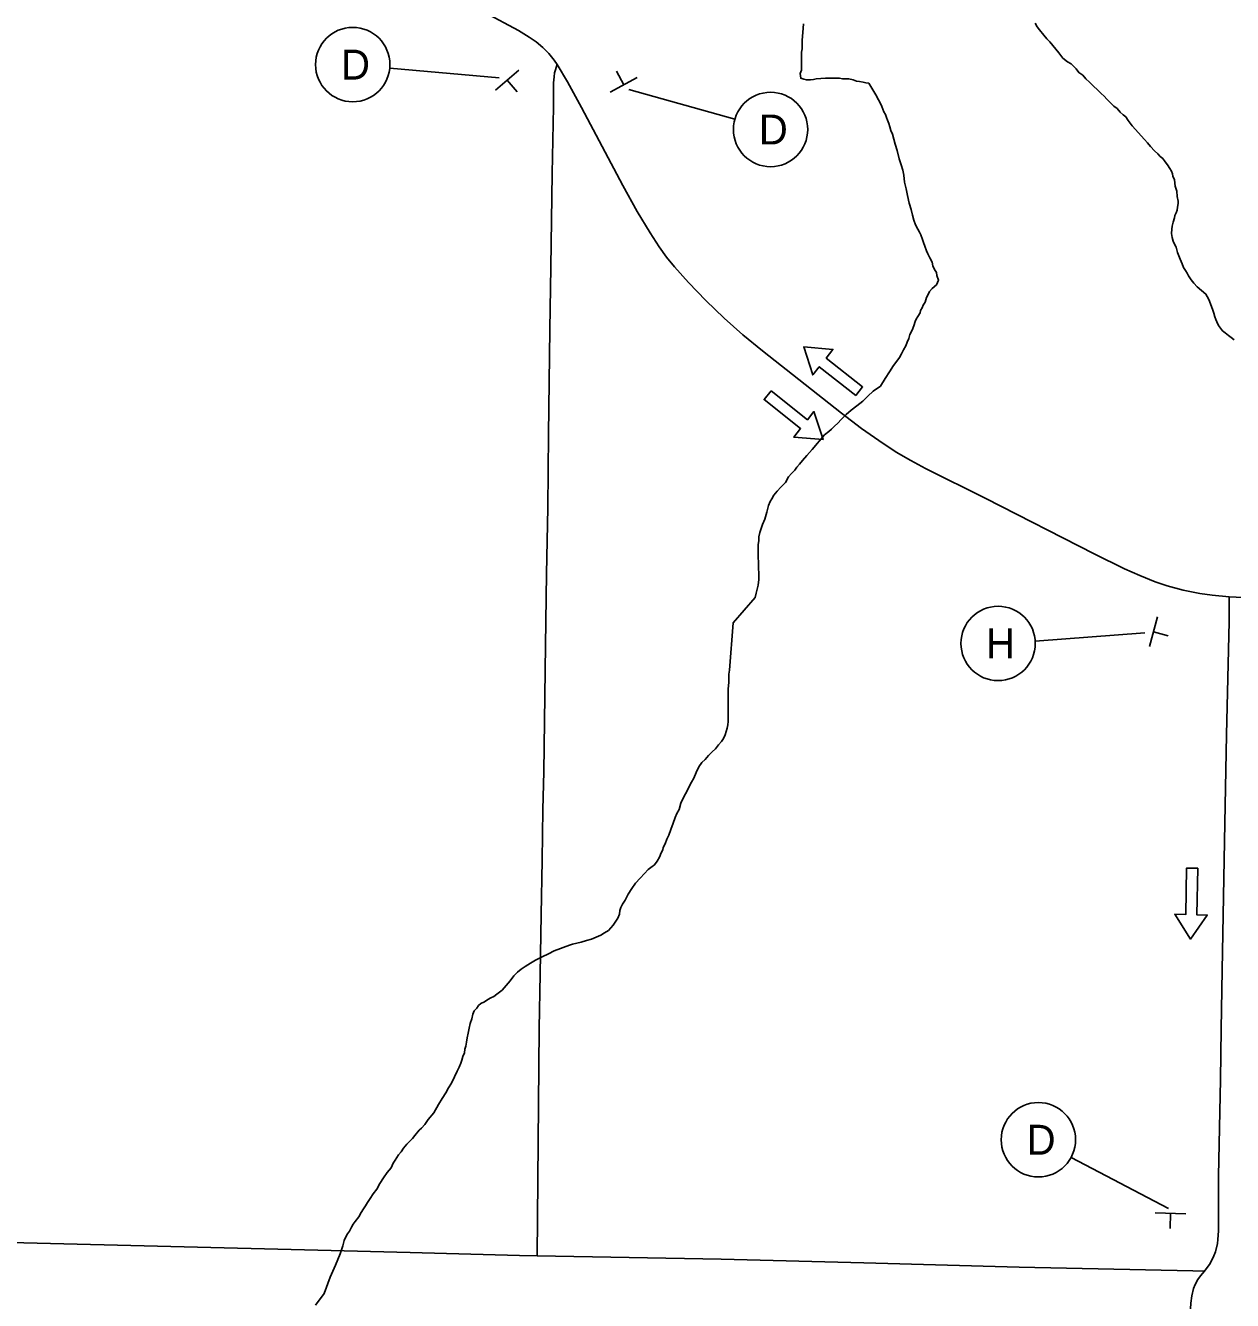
# Model space of a CAD drawing. Extents: x 1651.5 to 1685.5, y 1084.6 to 1106.6.
# Drawn here: x 1658.64 to 1664.92, y 1092.09 to 1098.72 of the extents above; entities that cross this region are included whole.
import ezdxf

# ---------------------------------------------------------------- set-up
doc = ezdxf.new("R2010")
doc.units = 0
for name, color, linetype in [('GM_X_County_Road', 7, 'Continuous'), ('GM_X_Minor_River', 7, 'Continuous'), ('GM_X_State_Route', 7, 'Continuous'), ('GM_X_Township_Road', 7, 'Continuous'), ('SH_Text', 7, 'Continuous'), ('SN_P_Signs', 7, 'Continuous')]:
    doc.layers.add(name, color=color, linetype=linetype)

msp = doc.modelspace()

# ---------------------------------------------------------------- linework, layer by layer
at = {"layer": 'GM_X_County_Road'}
for points in [[(1664.7781, 1092.2384), (1664.8083, 1092.279), (1664.8281, 1092.3184), (1664.8363, 1092.3391), (1664.8463, 1092.3822), (1664.8489, 1092.4043), (1664.8518, 1092.4484), (1664.852, 1092.7334), (1664.8626, 1093.2364), (1664.8652, 1093.499), (1664.8702, 1093.8051), (1664.8848, 1094.5707), (1664.8932, 1095.0301), (1664.908, 1095.6206), (1664.9075, 1095.7086), (1664.9073, 1095.7491)], [(1664.5833, 1088.7638), (1664.5876, 1088.9203), (1664.6035, 1089.4012), (1664.6207, 1089.904), (1664.6327, 1090.2091), (1664.6503, 1090.5818), (1664.6617, 1090.9095), (1664.6847, 1091.5685), (1664.6969, 1091.8932), (1664.7038, 1092.014), (1664.7085, 1092.0716), (1664.7131, 1092.1103), (1664.7212, 1092.1486), (1664.7305, 1092.1687), (1664.7444, 1092.1954), (1664.7575, 1092.2144), (1664.7781, 1092.2384)]]:
    msp.add_lwpolyline(points, dxfattribs=at)
at = {"layer": 'GM_X_Minor_River'}
for points in [[(1662.6906, 1098.7319), (1662.6874, 1098.6864), (1662.6842, 1098.6463), (1662.6839, 1098.6195), (1662.6836, 1098.6007), (1662.6807, 1098.5847), (1662.6806, 1098.5713), (1662.6802, 1098.5418), (1662.6795, 1098.4909), (1662.6739, 1098.4723), (1662.6763, 1098.4481), (1662.6924, 1098.4426), (1662.7058, 1098.4397), (1662.7273, 1098.4394), (1662.7434, 1098.4419), (1662.7568, 1098.4444), (1662.7811, 1098.4467), (1662.8052, 1098.4491), (1662.8214, 1098.4489), (1662.8375, 1098.4487), (1662.8509, 1098.4485), (1662.8777, 1098.4482), (1662.8938, 1098.4453), (1662.9072, 1098.4451), (1662.926, 1098.4449), (1662.9501, 1098.4392), (1662.9662, 1098.4336), (1662.9823, 1098.4307), (1663.001, 1098.4278), (1663.0144, 1098.4249), (1663.0305, 1098.4221), (1663.0673, 1098.3626), (1663.0804, 1098.3357), (1663.0909, 1098.3168), (1663.0988, 1098.3006), (1663.1092, 1098.2737), (1663.1171, 1098.2602), (1663.1223, 1098.2441), (1663.1274, 1098.2306), (1663.1353, 1098.2117), (1663.1404, 1098.1956), (1663.1456, 1098.1768), (1663.1534, 1098.1579), (1663.1611, 1098.1311), (1663.1688, 1098.1042), (1663.1791, 1098.0719), (1663.1894, 1098.0289), (1663.1997, 1097.9966), (1663.2074, 1097.9697), (1663.2124, 1097.9429), (1663.2174, 1097.908), (1663.225, 1097.8731), (1663.2326, 1097.8381), (1663.2402, 1097.7979), (1663.2505, 1097.7656), (1663.2582, 1097.736), (1663.2659, 1097.7091), (1663.2737, 1097.6849), (1663.2868, 1097.6633), (1663.2947, 1097.6471), (1663.3025, 1097.6336)], [(1663.8965, 1098.7348), (1663.907, 1098.7159), (1663.9202, 1098.6997), (1663.9414, 1098.6726), (1663.9572, 1098.6537), (1663.9731, 1098.6374), (1663.989, 1098.6184), (1664.0049, 1098.5995)], [(1664.0049, 1098.5995), (1664.0208, 1098.5805), (1664.0419, 1098.5535), (1664.0658, 1098.5344), (1664.0845, 1098.5234), (1664.0978, 1098.5099), (1664.111, 1098.4963), (1664.1242, 1098.4774), (1664.1455, 1098.4637), (1664.1614, 1098.4447), (1664.18, 1098.4284), (1664.2012, 1098.4067), (1664.2225, 1098.3877), (1664.241, 1098.3687), (1664.2569, 1098.3551), (1664.2702, 1098.3388), (1664.2887, 1098.3198), (1664.3073, 1098.3035), (1664.3233, 1098.2899), (1664.3391, 1098.271), (1664.3551, 1098.2574), (1664.3684, 1098.2465), (1664.3816, 1098.2275), (1664.4027, 1098.2005), (1664.4663, 1098.13), (1664.4821, 1098.1111), (1664.498, 1098.0921), (1664.5192, 1098.0704), (1664.5351, 1098.0541), (1664.5484, 1098.0405), (1664.5617, 1098.0297), (1664.5749, 1098.0134), (1664.5855, 1097.9972), (1664.5986, 1097.9783), (1664.6065, 1097.9648), (1664.6117, 1097.9513), (1664.6142, 1097.9379), (1664.6221, 1097.919), (1664.627, 1097.8868), (1664.6347, 1097.8599), (1664.6371, 1097.8331), (1664.6422, 1097.8089), (1664.642, 1097.7956), (1664.6391, 1097.7768), (1664.6362, 1097.7608), (1664.6306, 1097.7475), (1664.6251, 1097.7342), (1664.6223, 1097.7208), (1664.6166, 1097.6994), (1664.611, 1097.6781), (1664.6081, 1097.6621), (1664.6078, 1097.6406), (1664.6102, 1097.6192), (1664.6154, 1097.6004), (1664.6232, 1097.5842), (1664.6311, 1097.568), (1664.6388, 1097.5411), (1664.6518, 1097.5061), (1664.6622, 1097.4819), (1664.67, 1097.463), (1664.6806, 1097.4468), (1664.6885, 1097.4333), (1664.6963, 1097.4198), (1664.7095, 1097.3982), (1664.7227, 1097.382), (1664.7413, 1097.363), (1664.7625, 1097.344), (1664.7865, 1097.3249), (1664.7996, 1097.3006), (1664.8048, 1097.2871), (1664.8126, 1097.2683), (1664.8204, 1097.2468), (1664.8282, 1097.2252), (1664.8333, 1097.2064), (1664.8385, 1097.1929), (1664.8437, 1097.1795), (1664.8515, 1097.1606), (1664.8727, 1097.1336), (1664.886, 1097.1227), (1664.9046, 1097.1091), (1664.9179, 1097.0982), (1664.9338, 1097.0872)], [(1663.3025, 1097.6336), (1663.3103, 1097.6094), (1663.3155, 1097.5933), (1663.3233, 1097.5744), (1663.331, 1097.5502), (1663.3389, 1097.5341), (1663.3493, 1097.5125), (1663.3598, 1097.4909), (1663.365, 1097.4721), (1663.3728, 1097.4532), (1663.3833, 1097.437), (1663.3858, 1097.4209), (1663.3936, 1097.3967), (1663.3825, 1097.3728), (1663.3608, 1097.3543), (1663.3472, 1097.3384), (1663.3389, 1097.3198), (1663.3306, 1097.3065), (1663.325, 1097.2824), (1663.314, 1097.2665), (1663.3085, 1097.2532), (1663.3003, 1097.2399), (1663.2974, 1097.2265), (1663.2864, 1097.2079), (1663.2782, 1097.1947), (1663.2727, 1097.1813), (1663.2644, 1097.16), (1663.256, 1097.136), (1663.245, 1097.1147), (1663.2393, 1097.0934), (1663.2311, 1097.0747), (1663.2228, 1097.0561), (1663.2117, 1097.0348), (1663.2007, 1097.0135), (1663.1898, 1096.9949), (1663.1761, 1096.9763), (1663.1597, 1096.9525), (1663.1378, 1096.9206), (1663.1159, 1096.8861), (1663.0912, 1096.8462), (1663.0533, 1096.8199), (1663.0261, 1096.7935), (1662.9989, 1096.767), (1662.9691, 1096.7433), (1662.9392, 1096.7196), (1662.9121, 1096.6985), (1662.8876, 1096.6721), (1662.8686, 1096.6536), (1662.8523, 1096.6377), (1662.8359, 1096.6219), (1662.8223, 1096.6086), (1662.8007, 1096.5929), (1662.7352, 1096.516), (1662.708, 1096.4843), (1662.6862, 1096.4577), (1662.6698, 1096.4392), (1662.6562, 1096.4233), (1662.6453, 1096.4074), (1662.6289, 1096.3915), (1662.6126, 1096.373), (1662.5961, 1096.3437), (1662.5717, 1096.3199), (1662.5526, 1096.2988), (1662.5362, 1096.2776), (1662.5252, 1096.259), (1662.517, 1096.2457), (1662.5087, 1096.2243), (1662.5002, 1096.1896), (1662.489, 1096.1523), (1662.4779, 1096.1256), (1662.4696, 1096.1043), (1662.4639, 1096.083), (1662.4583, 1096.0616), (1662.458, 1096.0402), (1662.4551, 1096.0215), (1662.4548, 1096.0001), (1662.4545, 1095.9759), (1662.4542, 1095.9518), (1662.4566, 1095.9304), (1662.4563, 1095.9009), (1662.4585, 1095.8661), (1662.4582, 1095.8393), (1662.4551, 1095.8099), (1662.4495, 1095.7885), (1662.4438, 1095.7671), (1662.4382, 1095.7458), (1662.325, 1095.613)], [(1662.325, 1095.613), (1662.3047, 1095.3669), (1662.302, 1095.3455), (1662.3019, 1095.3241), (1662.3019, 1095.3027), (1662.2991, 1095.2706), (1662.2991, 1095.2465), (1662.299, 1095.2144), (1662.2989, 1095.1876), (1662.2989, 1095.1635), (1662.2988, 1095.1421), (1662.2988, 1095.1207), (1662.2987, 1095.0993), (1662.296, 1095.0833), (1662.2933, 1095.0646), (1662.2879, 1095.0485), (1662.2825, 1095.0298), (1662.2744, 1095.0111), (1662.2637, 1094.9951), (1662.2476, 1094.9791), (1662.2315, 1094.9577), (1662.2154, 1094.9417), (1662.1966, 1094.9231), (1662.1779, 1094.9017), (1662.1618, 1094.8857), (1662.1457, 1094.8644), (1662.1322, 1094.835), (1662.1188, 1094.8056), (1662.108, 1094.7842), (1662.0758, 1094.7228), (1662.065, 1094.7041), (1662.0516, 1094.6747), (1662.0435, 1094.6426), (1662.0301, 1094.6213), (1662.022, 1094.5999), (1662.0112, 1094.5705), (1662.0004, 1094.5384), (1661.9897, 1094.509), (1661.9789, 1094.4877), (1661.9708, 1094.4636), (1661.9601, 1094.4449), (1661.9574, 1094.4315), (1661.9493, 1094.4155), (1661.9412, 1094.3941), (1661.9278, 1094.3728), (1661.9144, 1094.3541), (1661.8956, 1094.3408), (1661.8822, 1094.3301), (1661.8634, 1094.3088), (1661.8393, 1094.2848), (1661.8151, 1094.2581), (1661.7964, 1094.2314), (1661.7776, 1094.202), (1661.7614, 1094.17), (1661.748, 1094.1486), (1661.7399, 1094.1326), (1661.7346, 1094.1166), (1661.7318, 1094.0978), (1661.7238, 1094.0765), (1661.7103, 1094.0551), (1661.6996, 1094.0391), (1661.6754, 1094.0124), (1661.654, 1093.9991), (1661.6353, 1093.9884), (1661.6111, 1093.9778), (1661.5871, 1093.9672), (1661.5603, 1093.9593), (1661.5335, 1093.9513), (1661.5094, 1093.946), (1661.488, 1093.9407), (1661.4719, 1093.9355), (1661.3916, 1093.9063), (1661.3621, 1093.8903), (1661.33, 1093.8744), (1661.2951, 1093.8584), (1661.2683, 1093.8425), (1661.2415, 1093.8238), (1661.2201, 1093.8105), (1661.2013, 1093.7945), (1661.1826, 1093.7759), (1661.1638, 1093.7492), (1661.1423, 1093.7251), (1661.1209, 1093.7011), (1661.1075, 1093.6905), (1661.094, 1093.6798), (1661.078, 1093.6692), (1661.0619, 1093.6612), (1661.0458, 1093.6532), (1661.0297, 1093.6399), (1661.011, 1093.6319), (1660.9976, 1093.6213), (1660.9895, 1093.6079), (1660.9761, 1093.5946), (1660.968, 1093.5759), (1660.9626, 1093.5518), (1660.9546, 1093.5278)], [(1660.9546, 1093.5278), (1660.9491, 1093.5037), (1660.9437, 1093.477), (1660.9383, 1093.4529), (1660.9356, 1093.4315), (1660.9329, 1093.4101), (1660.9275, 1093.3941), (1660.9248, 1093.3753), (1660.9167, 1093.3566), (1660.9113, 1093.3379), (1660.9059, 1093.3219), (1660.8979, 1093.3005), (1660.8871, 1093.2791), (1660.8737, 1093.2498), (1660.8575, 1093.2177), (1660.8414, 1093.1937), (1660.828, 1093.167), (1660.8092, 1093.1376), (1660.7904, 1093.1055), (1660.7662, 1093.0628), (1660.7367, 1093.0281), (1660.7179, 1093.0014), (1660.7018, 1092.9828), (1660.6884, 1092.9721), (1660.6669, 1092.9454), (1660.6535, 1092.9294), (1660.6401, 1092.9161), (1660.624, 1092.9001), (1660.6079, 1092.8787), (1660.5945, 1092.86), (1660.5811, 1092.844), (1660.573, 1092.8307), (1660.5649, 1092.8173), (1660.5542, 1092.8013), (1660.5434, 1092.7773), (1660.522, 1092.7532), (1660.5032, 1092.7239), (1660.4844, 1092.6945), (1660.4683, 1092.6651), (1660.4495, 1092.6411), (1660.4334, 1092.6171), (1660.4199, 1092.5957), (1660.4092, 1092.5797), (1660.3985, 1092.5637), (1660.3877, 1092.545), (1660.3743, 1092.5209), (1660.3555, 1092.4969), (1660.3448, 1092.4836), (1660.3367, 1092.4676), (1660.3259, 1092.4462), (1660.3152, 1092.4328), (1660.3071, 1092.4168), (1660.2991, 1092.3981), (1660.291, 1092.3714), (1660.2775, 1092.3286), (1660.2533, 1092.2698), (1660.2264, 1092.2084), (1660.1941, 1092.1229), (1660.1485, 1092.0615)]]:
    msp.add_lwpolyline(points, dxfattribs=at)
at = {"layer": 'GM_X_State_Route'}
msp.add_lwpolyline([(1661.0318, 1098.7896), (1661.2057, 1098.6964), (1661.2625, 1098.6625), (1661.2988, 1098.6371), (1661.3328, 1098.6089), (1661.3638, 1098.5772), (1661.3915, 1098.5427), (1661.4073, 1098.5194), (1661.4608, 1098.43), (1661.5345, 1098.2955), (1661.7495, 1097.8891), (1661.8236, 1097.7552), (1661.8913, 1097.643), (1661.9394, 1097.5702), (1661.9778, 1097.5174), (1662.019, 1097.4667), (1662.0914, 1097.3852), (1662.1827, 1097.2909), (1662.2772, 1097.2001), (1662.3754, 1097.1133), (1662.4764, 1097.0297), (1662.8888, 1096.7044), (1662.9935, 1096.6253), (1663.0824, 1096.5618), (1663.1739, 1096.5026), (1663.249, 1096.4581), (1663.326, 1096.417), (1663.6393, 1096.2607), (1664.2047, 1095.972), (1664.3617, 1095.8949), (1664.4414, 1095.859), (1664.5225, 1095.8271), (1664.5845, 1095.8067), (1664.6686, 1095.7839), (1664.7541, 1095.767), (1664.8187, 1095.7573), (1664.9073, 1095.7491), (1665.1676, 1095.737)], dxfattribs=at)
at = {"layer": 'GM_X_Township_Road'}
for points in [[(1661.3035, 1092.3184), (1661.3143, 1093.5021), (1661.3197, 1093.787), (1661.3248, 1094.0937), (1661.3296, 1094.3786), (1661.3338, 1094.6414), (1661.3381, 1094.8383), (1661.3464, 1095.4947), (1661.3524, 1095.8685), (1661.3584, 1096.2115), (1661.362, 1096.5938), (1661.3703, 1097.1408), (1661.3751, 1097.4654), (1661.381, 1097.9522), (1661.3883, 1098.3001), (1661.3882, 1098.4243), (1661.3919, 1098.4562), (1661.3943, 1098.4759), (1661.4073, 1098.5194)], [(1657.7657, 1092.4077), (1658.0405, 1092.3994), (1658.631, 1092.386), (1660.1619, 1092.3476), (1660.643, 1092.3358), (1661.2116, 1092.32), (1661.3035, 1092.3184)], [(1661.3035, 1092.3184), (1662.2614, 1092.3007), (1663.0049, 1092.2817), (1663.8141, 1092.2599), (1664.7189, 1092.2397), (1664.7781, 1092.2384)]]:
    msp.add_lwpolyline(points, dxfattribs=at)
at = {"layer": 'SH_Text'}
for p, q in [((1661.1065, 1098.4509), (1660.5357, 1098.5003)), ((1661.7812, 1098.3893), (1662.3331, 1098.2355)), ((1662.6917, 1097.0493), (1662.8442, 1097.0366)), ((1662.6917, 1097.0493), (1662.7389, 1096.9037)), ((1662.8442, 1097.0366), (1662.8089, 1096.9919)), ((1662.8089, 1096.9919), (1662.9986, 1096.8416)), ((1662.7389, 1096.9037), (1662.7728, 1096.9465)), ((1662.7728, 1096.9465), (1662.9625, 1096.7962)), ((1662.9986, 1096.8416), (1662.9625, 1096.7962)), ((1662.4854, 1096.7752), (1662.5214, 1096.8207)), ((1662.6751, 1096.6249), (1662.4854, 1096.7752)), ((1662.7111, 1096.6704), (1662.5214, 1096.8207)), ((1662.745, 1096.7131), (1662.7111, 1096.6704)), ((1662.7923, 1096.5675), (1662.745, 1096.7131)), ((1662.6397, 1096.5802), (1662.6751, 1096.6249)), ((1662.7923, 1096.5675), (1662.6397, 1096.5802)), ((1664.4687, 1095.5612), (1663.8974, 1095.5183)), ((1664.6809, 1094.0951), (1664.686, 1094.3371)), ((1664.686, 1094.3371), (1664.744, 1094.3359)), ((1664.7389, 1094.0939), (1664.744, 1094.3359)), ((1664.706, 1093.9671), (1664.6239, 1094.0963)), ((1664.6239, 1094.0963), (1664.6809, 1094.0951)), ((1664.706, 1093.9671), (1664.7935, 1094.0927)), ((1664.7935, 1094.0927), (1664.7389, 1094.0939)), ((1664.5916, 1092.5653), (1664.0841, 1092.8311))]:
    msp.add_line(p, q, dxfattribs=at)
for points in [[(1661.0318, 1098.7896), (1661.2057, 1098.6964), (1661.2625, 1098.6625), (1661.2988, 1098.6371), (1661.3328, 1098.6089), (1661.3638, 1098.5772), (1661.3915, 1098.5427), (1661.4073, 1098.5194), (1661.4608, 1098.43), (1661.5345, 1098.2955), (1661.7495, 1097.8891), (1661.8236, 1097.7552), (1661.8913, 1097.643), (1661.9394, 1097.5702), (1661.9778, 1097.5174), (1662.019, 1097.4667), (1662.0914, 1097.3852), (1662.1827, 1097.2909), (1662.2772, 1097.2001), (1662.3754, 1097.1133), (1662.4764, 1097.0297), (1662.8888, 1096.7044), (1662.9935, 1096.6253), (1663.0824, 1096.5618), (1663.1739, 1096.5026), (1663.249, 1096.4581), (1663.326, 1096.417), (1663.6393, 1096.2607), (1664.2047, 1095.972), (1664.3617, 1095.8949), (1664.4414, 1095.859), (1664.5225, 1095.8271), (1664.5845, 1095.8067), (1664.6686, 1095.7839), (1664.7541, 1095.767), (1664.8187, 1095.7573), (1664.9073, 1095.7491)], [(1664.7781, 1092.2384), (1664.8083, 1092.279), (1664.8281, 1092.3184), (1664.8363, 1092.3391), (1664.8463, 1092.3822), (1664.8489, 1092.4043), (1664.8518, 1092.4484), (1664.852, 1092.7334), (1664.8626, 1093.2364), (1664.8652, 1093.499), (1664.8702, 1093.8051), (1664.8848, 1094.5707), (1664.8932, 1095.0301), (1664.908, 1095.6206), (1664.9075, 1095.7086), (1664.9073, 1095.7491)], [(1664.5833, 1088.7638), (1664.5876, 1088.9203), (1664.6035, 1089.4012), (1664.6207, 1089.904), (1664.6327, 1090.2091), (1664.6503, 1090.5818), (1664.6617, 1090.9095), (1664.6847, 1091.5685), (1664.6969, 1091.8932), (1664.7038, 1092.014), (1664.7085, 1092.0716), (1664.7131, 1092.1103), (1664.7212, 1092.1486), (1664.7305, 1092.1687), (1664.7444, 1092.1954), (1664.7575, 1092.2144), (1664.7781, 1092.2384)]]:
    msp.add_lwpolyline(points, dxfattribs=at)
for points in [[(1662.9625, 1096.7962), (1662.7728, 1096.9465), (1662.7389, 1096.9037), (1662.6917, 1097.0493), (1662.8442, 1097.0366), (1662.8089, 1096.9919), (1662.9986, 1096.8416)], [(1662.5214, 1096.8207), (1662.7111, 1096.6704), (1662.745, 1096.7131), (1662.7923, 1096.5675), (1662.6397, 1096.5802), (1662.6751, 1096.6249), (1662.4854, 1096.7752)], [(1664.744, 1094.3359), (1664.7389, 1094.0939), (1664.7935, 1094.0927), (1664.706, 1093.9671), (1664.6239, 1094.0963), (1664.6809, 1094.0951), (1664.686, 1094.3371)]]:
    msp.add_lwpolyline(points, close=True, dxfattribs=at)
for centre in [(1660.3431, 1098.5192), (1662.519, 1098.1814), (1663.7042, 1095.5061), (1663.9137, 1092.9229)]:
    msp.add_circle(centre, 0.1936, dxfattribs=at)
at = {"layer": 'SN_P_Signs'}
for p, q in [((1661.2083, 1098.4896), (1661.0859, 1098.3866)), ((1661.7546, 1098.414), (1661.7162, 1098.4841)), ((1661.1471, 1098.4381), (1661.1986, 1098.3768)), ((1661.6844, 1098.3756), (1661.8248, 1098.4524)), ((1664.5336, 1095.6443), (1664.4919, 1095.4899)), ((1664.5128, 1095.5671), (1664.59, 1095.5462)), ((1664.6818, 1092.538), (1664.5219, 1092.5422)), ((1664.6018, 1092.5401), (1664.5998, 1092.4601))]:
    msp.add_line(p, q, dxfattribs=at)

# ---------------------------------------------------------------- texts
at = {"layer": 'SH_Text'}
for s, p in [('D', (1660.2823, 1098.4412)), ('D', (1662.4582, 1098.1034)), ('H', (1663.6409, 1095.4281)), ('D', (1663.8529, 1092.8449))]:
    msp.add_text(s, height=0.156, dxfattribs=at).set_placement(p)

doc.saveas('drawing.dxf')
